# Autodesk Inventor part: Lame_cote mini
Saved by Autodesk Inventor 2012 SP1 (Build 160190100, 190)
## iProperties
Created: 2014-12
Part Number: Lame_cote mini
Material: Default
Document SubType Name: Modeling
Designer: Bruno
Density: 1 g/cm^3
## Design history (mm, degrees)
node "Lame_cote mini1"
node "Lame_cote mini"
node "Base1"
